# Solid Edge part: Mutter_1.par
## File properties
Dokumentum tartalom típus: 0
Last saved by: ahadarics
Revision: 76
Sűrűség: 0,000 kg/m^3
Pontosság: 0,990
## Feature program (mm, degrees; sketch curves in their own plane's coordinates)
base feature "unnamed BaseFeature 1"
thread "unnamed Thread 1"
chamfer "Letörés_1"  SetBackValue2 = 60 deg
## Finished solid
Body 1: solid body, 23 faces, 46 edges, 24 vertices.
  Faces by surface: cone 14, plane 8, cylinder 1
  Edges by curve: spline 24, circle 16, line 6
Bounding box of the edges (mm): 7.000 x 21.939 x 19.000, from (0, -10.9697, -9.5) to (7, 10.9697, 9.5).
Cylindrical faces by radius (mm): R5.3235 x1
Conical faces (half-angle, radius in mm at the cone's reference point): 60 deg R5.3235 x1, 60 deg R6.0163 x1, 60 deg R10.2348 x12
Planar faces by outward normal: +x 1, +z 1, -x 1, -z 1, oblique 4
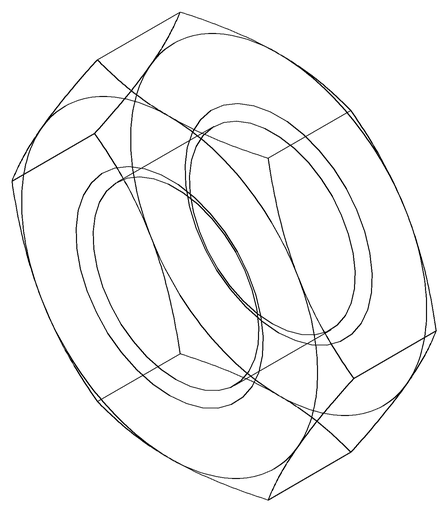
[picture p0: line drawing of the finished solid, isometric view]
